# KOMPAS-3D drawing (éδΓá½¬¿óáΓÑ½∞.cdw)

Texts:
  Выталкиватель
  Текст на чертеже
  Размерные надписи
  Шероховатость
  Линия-выноска #1
  Линия-выноска #2
  Линия-выноска #3
  Отклонения формы и база
  Заголовок таблицы
  Ячейка таблицы
  Стрелка вида
  Обозначение изменения
  Фигурная скобка
  Номер узла
  Марка координационной оси
  VRCB
  Выносная надпись
  Обозначение узла
  Марка/позиционное обозначение с линией-выноской
  Марка/позиционное обозначение на линии
  Марка/позиционное обозначение без линии-выноски
  Ra 0,8
  1.HRC 59...61.
  Ra 3,2
Dimensions and other numbers on the sheet: 7; 85,5; 75,5; 14; 5,2; 9,8; 0,05; 1; 2,6; 1:1; 0; 2; 3; 4; 5; 6; 8; 9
